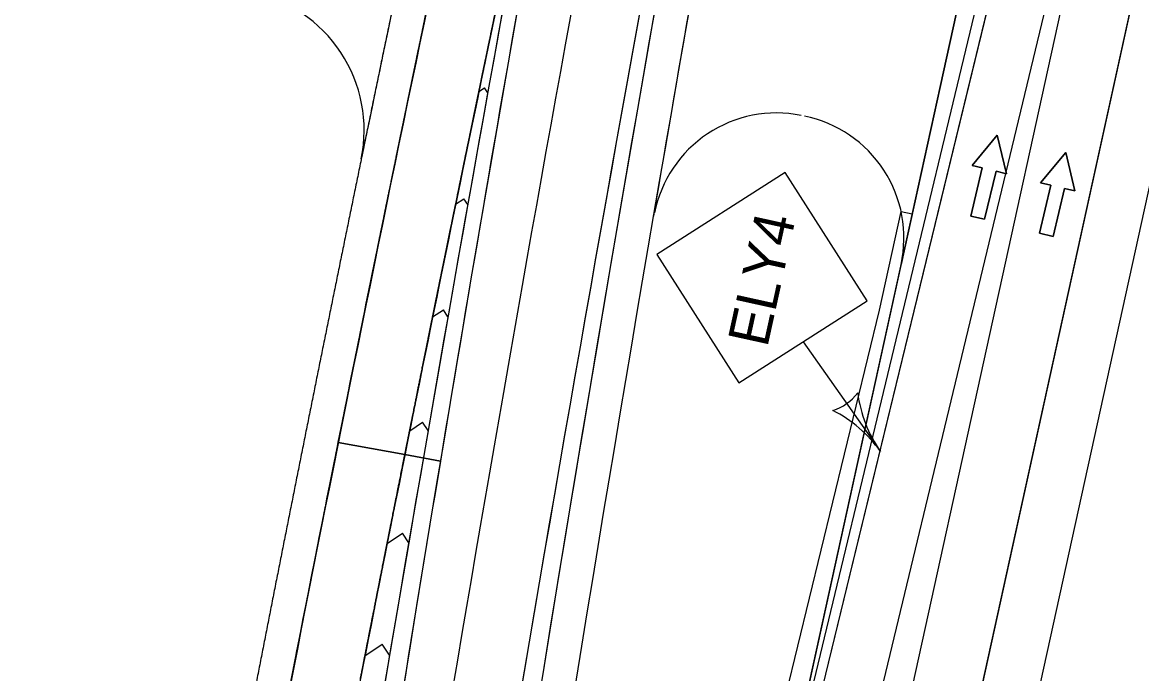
# Model space of a CAD drawing. Extents: x 14104283 to 14120882, y 8635219 to 8671666.
# Drawn here: x 14107950.2 to 14108148.5, y 8640439.5 to 8640554.9 of the extents above; entities that cross this region are included whole.
import ezdxf

# ---------------------------------------------------------------- set-up
doc = ezdxf.new("R2010")
doc.units = 0
for name, color, linetype in [('Cell', 7, 'Continuous'), ('dsnPaintExistingBrokenLaneLineWhite', 7, 'Continuous'), ('dsnPaintExistingChannelizingLaneWhite', 7, 'Continuous'), ('dsnPaintExistingEdgeLineRightWhite', 7, 'Continuous'), ('dsnPaintPlaceBrokenLaneLineWhite', 7, 'Continuous'), ('dsnPaintPlaceEdgeLineLeftYellow', 7, 'Continuous'), ('dsnPaintPlaceEdgeLineRightWhite', 7, 'Continuous'), ('dsnShadingPaved', 7, 'Continuous'), ('dsnStdLabel', 7, 'Continuous'), ('dsnStgShadingPrevPav', 7, 'Continuous'), ('dsnTapeRemoveChannelizingWhite', 7, 'Continuous'), ('dsnTapeRemoveChannelizingYellow', 7, 'Continuous')]:
    doc.layers.add(name, color=color, linetype=linetype)

msp = doc.modelspace()

# ---------------------------------------------------------------- linework, layer by layer
at = {"layer": 'Cell'}
for points in [[(14108120.71, 8640519.98), (14108118.28, 8640520.56), (14108120.3, 8640529.07), (14108118.48, 8640529.51), (14108122.96, 8640534.87), (14108124.56, 8640528.06), (14108122.73, 8640528.5)], [(14108132.84, 8640516.93), (14108130.41, 8640517.5), (14108132.43, 8640526.02), (14108130.61, 8640526.45), (14108135.09, 8640531.81), (14108136.69, 8640525.01), (14108134.86, 8640525.44)]]:
    msp.add_lwpolyline(points, close=True, dxfattribs=at)
for points in [[(14108122.73, 8640528.5), (14108124.56, 8640528.06), (14108122.96, 8640534.87), (14108118.48, 8640529.51), (14108120.3, 8640529.07), (14108118.28, 8640520.56), (14108120.71, 8640519.98), (14108122.73, 8640528.5)], [(14108134.86, 8640525.44), (14108136.69, 8640525.01), (14108135.09, 8640531.81), (14108130.61, 8640526.45), (14108132.43, 8640526.02), (14108130.41, 8640517.5), (14108132.84, 8640516.93), (14108134.86, 8640525.44)]]:
    msp.add_lwpolyline(points, dxfattribs=at)
at = {"layer": 'dsnPaintExistingBrokenLaneLineWhite'}
msp.add_arc((14117394.14, 8638857.08), 9500, 167.610212, 171.325989, dxfattribs=at)
at = {"layer": 'dsnPaintExistingChannelizingLaneWhite'}
for p, q in [((14108031.08, 8640542.65), (14108032.04, 8640543.28)), ((14108032.63, 8640542.38), (14108032.04, 8640543.28)), ((14108026.95, 8640522.65), (14108028.41, 8640523.61)), ((14108029.08, 8640522.59), (14108028.41, 8640523.61)), ((14108022.87, 8640502.69), (14108024.77, 8640503.94)), ((14108025.58, 8640502.72), (14108024.77, 8640503.94)), ((14108018.8, 8640482.51), (14108021.1, 8640484.04)), ((14108022.06, 8640482.58), (14108021.1, 8640484.04)), ((14108014.81, 8640462.56), (14108017.51, 8640464.36)), ((14108018.63, 8640462.68), (14108017.51, 8640464.36)), ((14108010.88, 8640442.64), (14108013.92, 8640444.69)), ((14108015.24, 8640442.73), (14108013.92, 8640444.69))]:
    msp.add_line(p, q, dxfattribs=at)
for centre, radius, start, end in [((14117394.14, 8638857.08), 9512, 169.444425, 171.325989), ((14117342.69, 8638609.63), 9510.13, 167.921867, 168.915877)]:
    msp.add_arc(centre, radius, start, end, dxfattribs=at)
at = {"layer": 'dsnPaintExistingEdgeLineRightWhite'}
for centre, radius, start, end in [((14117342.69, 8638609.63), 9522.13, 167.509575, 168.915877), ((14117350.61, 8638608.07), 9530.2, 168.915826, 170.320937)]:
    msp.add_arc(centre, radius, start, end, dxfattribs=at)
at = {"layer": 'dsnPaintPlaceBrokenLaneLineWhite'}
msp.add_line((14108099.08, 8640397.01), (14108184.86, 8640787.53), dxfattribs=at)
at = {"layer": 'dsnPaintPlaceEdgeLineLeftYellow'}
msp.add_line((14108046.49, 8640249.83), (14108129.2, 8640590.05), dxfattribs=at)
msp.add_arc((14117502.5, 8638839.63), 9597.75, 167.26751, 171.3206, dxfattribs=at)
at = {"layer": 'dsnPaintPlaceEdgeLineRightWhite'}
msp.add_line((14108110.8, 8640394.44), (14108196.58, 8640784.95), dxfattribs=at)
at = {"layer": 'dsnShadingPaved'}
msp.add_lwpolyline([(14108083.12, 8640400.52), (14108129.2, 8640590.05), (14108151.72, 8640692.57), (14108163.38, 8640689.76), (14108196.58, 8640784.95), (14108110.8, 8640394.44)], close=True, dxfattribs=at)
for centre, radius, start, end in [((14117502.5, 8638839.63), 9597.75, 167.266653, 171.3206), ((14117394.14, 8638857.08), 9512, 167.610212, 171.325989), ((14117394.14, 8638857.08), 9500, 167.610212, 171.325989), ((14117394.14, 8638857.08), 9500, 167.610212, 171.325989), ((14117342.69, 8638609.63), 9522.13, 167.509575, 168.915877), ((14117342.69, 8638609.63), 9510.13, 167.921867, 168.915877), ((14117350.61, 8638608.07), 9530.2, 168.915826, 170.320937)]:
    msp.add_arc(centre, radius, start, end, dxfattribs=at)
at = {"layer": 'dsnStdLabel'}
msp.add_line((14108088.52, 8640498.27), (14108102.24, 8640478.84), dxfattribs=at)
msp.add_lwpolyline([(14108077.14, 8640491), (14108099.89, 8640505.55), (14108085.34, 8640528.29), (14108062.59, 8640513.74)], close=True, dxfattribs=at)
for centre, radius, start, end in [((14108091.14, 8640494.55), 8.86, 287.4986, 322.9671), ((14108120.99, 8640492.08), 22.95, 187.1617, 215.233), ((14108083.5, 8640465.6), 22.95, 35.2328, 63.3041)]:
    msp.add_arc(centre, radius, start, end, dxfattribs=at)
at = {"layer": 'dsnStgShadingPrevPav'}
for p, q in [((14108124.35, 8640595.95), (14108105.9, 8640511.97)), ((14108006.14, 8640480.41), (14108017.94, 8640478.29)), ((14108017.94, 8640478.29), (14108006.14, 8640480.41)), ((14108017.94, 8640478.29), (14108024.25, 8640477.15)), ((14108024.25, 8640477.15), (14108017.94, 8640478.29))]:
    msp.add_line(p, q, dxfattribs=at)
for points in [[(14108081.5, 8640400.87), (14108123.34, 8640591.33), (14108126.55, 8640605.98), (14108216.67, 8641016.2), (14108268.16, 8641250.61), (14108382.95, 8641773.15), (14108422.02, 8641764.57), (14108309.38, 8641251.8), (14108270.22, 8641073.55), (14108265.93, 8641054.01), (14108255.74, 8641007.62), (14108202.1, 8640763.44), (14108120.56, 8640392.29)], [(14108077.26, 8640401.8), (14108102.07, 8640503.86), (14108105.91, 8640521.35), (14108107.87, 8640520.92), (14108081.5, 8640400.87)]]:
    msp.add_lwpolyline(points, close=True, dxfattribs=at)
for centre, radius, start, end in [((14117407.82, 8638919.35), 9488, 167.610212, 172.222077), ((14117407.82, 8638919.35), 9482, 167.610212, 172.222077), ((14117407.82, 8638919.35), 9512, 169.413861, 172.222077), ((14117407.82, 8638919.35), 9512, 169.413861, 170.574102), ((14117407.82, 8638919.35), 9488, 169.413861, 172.222077), ((14117407.82, 8638919.35), 9482, 169.768725, 170.278029), ((14107985.74, 8640535.75), 25, 348.3681, 78.5089), ((14108083.79, 8640516.82), 22, 78.4908, 168.7454), ((14108084.41, 8640516.69), 22, 347.6102, 78.4908), ((14117407.82, 8638919.35), 9512, 170.574102, 171.702544)]:
    msp.add_arc(centre, radius, start, end, dxfattribs=at)
for points, degree in [([(14108040.07, 8640670.33), (14108039.11, 8640666.01), (14108035.79, 8640651.03), (14108029.85, 8640623.7), (14108025.19, 8640602.04), (14108020.26, 8640578.84), (14108015.47, 8640556.04), (14108010.72, 8640533.12), (14108006.03, 8640510.22), (14108001.39, 8640487.29), (14107996.81, 8640464.36), (14107992.28, 8640441.41), (14107987.82, 8640418.46), (14107983.4, 8640395.49), (14107979.05, 8640372.51), (14107974.75, 8640349.53), (14107970.51, 8640326.51), (14107966.33, 8640303.59), (14107962.15, 8640280.24), (14107958.29, 8640258.43), (14107953.48, 8640230.88), (14107950.9, 8640215.75), (14107950.15, 8640211.39)], 2), ([(14107956.07, 8640210.37), (14107957.38, 8640218.06), (14107960.02, 8640233.43), (14107964.04, 8640256.47), (14107968.11, 8640279.5), (14107972.24, 8640302.51), (14107976.42, 8640325.52), (14107980.66, 8640348.51), (14107984.96, 8640371.49), (14107989.32, 8640394.46), (14107993.73, 8640417.41), (14107998.19, 8640440.35), (14108002.71, 8640463.28), (14108007.29, 8640486.2), (14108011.92, 8640509.1), (14108016.61, 8640531.99), (14108021.36, 8640554.87), (14108026.16, 8640577.73), (14108031.01, 8640600.58), (14108035.93, 8640623.41), (14108040.89, 8640646.24), (14108044.25, 8640661.44), (14108045.92, 8640669.04)], 3), ([(14108026.65, 8640608.79), (14108026.14, 8640606.46), (14108024.06, 8640596.74), (14108020.26, 8640578.84), (14108015.47, 8640556.04), (14108012.14, 8640539.95), (14108010.4, 8640531.51), (14108010.23, 8640530.71)], 3), ([(14108034.62, 8640559.66), (14108034.22, 8640557.75), (14108033.82, 8640555.85), (14108033.43, 8640553.95)], 2), ([(14108033.43, 8640553.95), (14108033.82, 8640555.85), (14108034.22, 8640557.75), (14108034.62, 8640559.66)], 2), ([(14108021.37, 8640554.87), (14108021.45, 8640555.25), (14108021.52, 8640555.63), (14108021.6, 8640556.01)], 2), ([(14108020.17, 8640549.15), (14108020.57, 8640551.05), (14108020.97, 8640552.96), (14108021.37, 8640554.87)], 2), ([(14108033.43, 8640553.95), (14108033.35, 8640553.57), (14108033.27, 8640553.19), (14108033.19, 8640552.81)], 2), ([(14108033.19, 8640552.81), (14108033.27, 8640553.19), (14108033.35, 8640553.57), (14108033.43, 8640553.95)], 2), ([(14108033.19, 8640552.81), (14108032.87, 8640551.28), (14108032.55, 8640549.76), (14108032.24, 8640548.24)], 2), ([(14108032.24, 8640548.24), (14108032.55, 8640549.76), (14108032.87, 8640551.28), (14108033.19, 8640552.81)], 2), ([(14108019.7, 8640546.86), (14108019.78, 8640547.24), (14108019.86, 8640547.62), (14108019.94, 8640548)], 2), ([(14108019.94, 8640548), (14108020.02, 8640548.39), (14108020.09, 8640548.77), (14108020.17, 8640549.15)], 2), ([(14108032.24, 8640548.24), (14108032.16, 8640547.86), (14108032.08, 8640547.48), (14108032, 8640547.1)], 2), ([(14108032, 8640547.1), (14108032.08, 8640547.48), (14108032.16, 8640547.86), (14108032.24, 8640548.24)], 2), ([(14108018.99, 8640543.43), (14108019.22, 8640544.57), (14108019.46, 8640545.72), (14108019.7, 8640546.86)], 2), ([(14108032, 8640547.1), (14108031.84, 8640546.33), (14108031.68, 8640545.57), (14108031.52, 8640544.81)], 2), ([(14108031.52, 8640544.81), (14108031.68, 8640545.57), (14108031.84, 8640546.33), (14108032, 8640547.1)], 2), ([(14108018.75, 8640542.29), (14108018.83, 8640542.67), (14108018.91, 8640543.05), (14108018.99, 8640543.43)], 2), ([(14108031.52, 8640544.81), (14108031.21, 8640543.29), (14108030.89, 8640541.77), (14108030.57, 8640540.24)], 2), ([(14108030.57, 8640540.24), (14108030.89, 8640541.77), (14108031.21, 8640543.29), (14108031.52, 8640544.81)], 2), ([(14108018.28, 8640540), (14108018.43, 8640540.76), (14108018.59, 8640541.52), (14108018.75, 8640542.29)], 2), ([(14108017.33, 8640535.42), (14108017.64, 8640536.95), (14108017.96, 8640538.47), (14108018.28, 8640540)], 2), ([(14108030.57, 8640540.24), (14108030.42, 8640539.48), (14108030.26, 8640538.72), (14108030.1, 8640537.96)], 2), ([(14108030.1, 8640537.96), (14108030.26, 8640538.72), (14108030.42, 8640539.48), (14108030.57, 8640540.24)], 2), ([(14108030.1, 8640537.96), (14108029.71, 8640536.05), (14108029.31, 8640534.15), (14108028.92, 8640532.24)], 2), ([(14108028.92, 8640532.24), (14108029.31, 8640534.15), (14108029.71, 8640536.05), (14108030.1, 8640537.96)], 2), ([(14108016.86, 8640533.13), (14108017.01, 8640533.9), (14108017.17, 8640534.66), (14108017.33, 8640535.42)], 2), ([(14108016.39, 8640530.85), (14108016.46, 8640531.23), (14108016.54, 8640531.61), (14108016.62, 8640531.99)], 2), ([(14108016.62, 8640531.99), (14108016.7, 8640532.37), (14108016.78, 8640532.75), (14108016.86, 8640533.13)], 2), ([(14108028.92, 8640532.24), (14108028.76, 8640531.48), (14108028.6, 8640530.72), (14108028.45, 8640529.96)], 2), ([(14108028.45, 8640529.96), (14108028.6, 8640530.72), (14108028.76, 8640531.48), (14108028.92, 8640532.24)], 2), ([(14108014.97, 8640523.98), (14108015.44, 8640526.27), (14108015.91, 8640528.56), (14108016.39, 8640530.85)], 2), ([(14108028.45, 8640529.96), (14108028.37, 8640529.58), (14108028.29, 8640529.2), (14108028.21, 8640528.82)], 2), ([(14108028.21, 8640528.82), (14108028.29, 8640529.2), (14108028.37, 8640529.58), (14108028.45, 8640529.96)], 2), ([(14108028.21, 8640528.82), (14108027.82, 8640526.91), (14108027.43, 8640525.01), (14108027.04, 8640523.1)], 2), ([(14108027.04, 8640523.1), (14108027.43, 8640525.01), (14108027.82, 8640526.91), (14108028.21, 8640528.82)], 2), ([(14108014.74, 8640522.84), (14108014.82, 8640523.22), (14108014.9, 8640523.6), (14108014.97, 8640523.98)], 2), ([(14108013.33, 8640515.97), (14108013.8, 8640518.26), (14108014.27, 8640520.55), (14108014.74, 8640522.84)], 2), ([(14108027.04, 8640523.1), (14108026.72, 8640521.58), (14108026.41, 8640520.05), (14108026.1, 8640518.53)], 2), ([(14108026.1, 8640518.53), (14108026.41, 8640520.05), (14108026.72, 8640521.58), (14108027.04, 8640523.1)], 2), ([(14108026.1, 8640518.53), (14108026.02, 8640518.15), (14108025.94, 8640517.77), (14108025.86, 8640517.39)], 2), ([(14108025.86, 8640517.39), (14108025.94, 8640517.77), (14108026.02, 8640518.15), (14108026.1, 8640518.53)], 2), ([(14108012.4, 8640511.39), (14108012.71, 8640512.92), (14108013.02, 8640514.44), (14108013.33, 8640515.97)], 2), ([(14108025.86, 8640517.39), (14108025.71, 8640516.63), (14108025.55, 8640515.86), (14108025.4, 8640515.1)], 2), ([(14108025.4, 8640515.1), (14108025.55, 8640515.86), (14108025.71, 8640516.63), (14108025.86, 8640517.39)], 2), ([(14108025.4, 8640515.1), (14108025.24, 8640514.34), (14108025.09, 8640513.58), (14108024.93, 8640512.81)], 2), ([(14108024.93, 8640512.81), (14108025.09, 8640513.58), (14108025.24, 8640514.34), (14108025.4, 8640515.1)], 2), ([(14108024.93, 8640512.81), (14108024.7, 8640511.67), (14108024.46, 8640510.53), (14108024.23, 8640509.38)], 2), ([(14108024.23, 8640509.38), (14108024.46, 8640510.53), (14108024.7, 8640511.67), (14108024.93, 8640512.81)], 2), ([(14108011.93, 8640509.1), (14108012.01, 8640509.48), (14108012.09, 8640509.86), (14108012.17, 8640510.25)], 2), ([(14108012.17, 8640510.25), (14108012.24, 8640510.63), (14108012.32, 8640511.01), (14108012.4, 8640511.39)], 2), ([(14108011.47, 8640506.81), (14108011.62, 8640507.57), (14108011.78, 8640508.34), (14108011.93, 8640509.1)], 2), ([(14108024, 8640508.24), (14108023.92, 8640507.86), (14108023.84, 8640507.48), (14108023.76, 8640507.1)], 2), ([(14108023.76, 8640507.1), (14108023.84, 8640507.48), (14108023.92, 8640507.86), (14108024, 8640508.24)], 2), ([(14108024.23, 8640509.38), (14108024.15, 8640509), (14108024.07, 8640508.62), (14108024, 8640508.24)], 2), ([(14108024, 8640508.24), (14108024.07, 8640508.62), (14108024.15, 8640509), (14108024.23, 8640509.38)], 2), ([(14108010.77, 8640503.38), (14108011, 8640504.52), (14108011.23, 8640505.67), (14108011.47, 8640506.81)], 2), ([(14108023.53, 8640505.95), (14108023.45, 8640505.57), (14108023.38, 8640505.19), (14108023.3, 8640504.81)], 2), ([(14108023.3, 8640504.81), (14108023.38, 8640505.19), (14108023.45, 8640505.57), (14108023.53, 8640505.95)], 2), ([(14108023.76, 8640507.1), (14108023.69, 8640506.72), (14108023.61, 8640506.34), (14108023.53, 8640505.95)], 2), ([(14108023.53, 8640505.95), (14108023.61, 8640506.34), (14108023.69, 8640506.72), (14108023.76, 8640507.1)], 2), ([(14108023.07, 8640503.67), (14108022.99, 8640503.29), (14108022.91, 8640502.91), (14108022.83, 8640502.52)], 2), ([(14108022.83, 8640502.52), (14108022.91, 8640502.91), (14108022.99, 8640503.29), (14108023.07, 8640503.67)], 2), ([(14108023.3, 8640504.81), (14108023.22, 8640504.43), (14108023.14, 8640504.05), (14108023.07, 8640503.67)], 2), ([(14108023.07, 8640503.67), (14108023.14, 8640504.05), (14108023.22, 8640504.43), (14108023.3, 8640504.81)], 2), ([(14108010.3, 8640501.09), (14108010.46, 8640501.85), (14108010.61, 8640502.61), (14108010.77, 8640503.38)], 2), ([(14108022.83, 8640502.52), (14108022.76, 8640502.14), (14108022.68, 8640501.76), (14108022.6, 8640501.38)], 2), ([(14108022.6, 8640501.38), (14108022.68, 8640501.76), (14108022.76, 8640502.14), (14108022.83, 8640502.52)], 2), ([(14108009.38, 8640496.5), (14108009.69, 8640498.03), (14108009.99, 8640499.56), (14108010.3, 8640501.09)], 2), ([(14108022.37, 8640500.24), (14108021.98, 8640498.33), (14108021.6, 8640496.43), (14108021.21, 8640494.52)], 2), ([(14108021.21, 8640494.52), (14108021.6, 8640496.43), (14108021.98, 8640498.33), (14108022.37, 8640500.24)], 2), ([(14108022.6, 8640501.38), (14108022.52, 8640501), (14108022.45, 8640500.62), (14108022.37, 8640500.24)], 2), ([(14108022.37, 8640500.24), (14108022.45, 8640500.62), (14108022.52, 8640501), (14108022.6, 8640501.38)], 2), ([(14108009.15, 8640495.36), (14108009.22, 8640495.74), (14108009.3, 8640496.12), (14108009.38, 8640496.5)], 2), ([(14108008.45, 8640491.92), (14108008.68, 8640493.07), (14108008.91, 8640494.21), (14108009.15, 8640495.36)], 2), ([(14108021.21, 8640494.52), (14108020.52, 8640491.09), (14108019.83, 8640487.66), (14108019.14, 8640484.22)], 2), ([(14108019.14, 8640484.22), (14108019.83, 8640487.66), (14108020.52, 8640491.09), (14108021.21, 8640494.52)], 2), ([(14108007.99, 8640489.63), (14108008.14, 8640490.4), (14108008.3, 8640491.16), (14108008.45, 8640491.92)], 2), ([(14108007.53, 8640487.34), (14108007.61, 8640487.72), (14108007.68, 8640488.11), (14108007.76, 8640488.49)], 2), ([(14108007.76, 8640488.49), (14108007.84, 8640488.87), (14108007.91, 8640489.25), (14108007.99, 8640489.63)], 2), ([(14108006.84, 8640483.91), (14108006.99, 8640484.67), (14108007.15, 8640485.43), (14108007.3, 8640486.2)], 2), ([(14108007.3, 8640486.2), (14108007.38, 8640486.58), (14108007.45, 8640486.96), (14108007.53, 8640487.34)], 2), ([(14108006.38, 8640481.61), (14108006.53, 8640482.38), (14108006.69, 8640483.14), (14108006.84, 8640483.91)], 2), ([(14108019.14, 8640484.22), (14108019.06, 8640483.84), (14108018.98, 8640483.46), (14108018.91, 8640483.08)], 2), ([(14108018.91, 8640483.08), (14108018.98, 8640483.46), (14108019.06, 8640483.84), (14108019.14, 8640484.22)], 2), ([(14108018.91, 8640483.08), (14108018.75, 8640482.32), (14108018.6, 8640481.55), (14108018.45, 8640480.79)], 2), ([(14108018.45, 8640480.79), (14108018.6, 8640481.55), (14108018.75, 8640482.32), (14108018.91, 8640483.08)], 2), ([(14108005.46, 8640477.03), (14108005.69, 8640478.16), (14108005.91, 8640479.28), (14108006.14, 8640480.41)], 2), ([(14108006.14, 8640480.41), (14108006.22, 8640480.81), (14108006.3, 8640481.21), (14108006.38, 8640481.61)], 2), ([(14108018.45, 8640480.79), (14108018.29, 8640480.03), (14108018.14, 8640479.27), (14108017.99, 8640478.5)], 2), ([(14108017.99, 8640478.5), (14108018.14, 8640479.27), (14108018.29, 8640480.03), (14108018.45, 8640480.79)], 2), ([(14108017.94, 8640478.29), (14108017.88, 8640477.98), (14108017.82, 8640477.67), (14108017.76, 8640477.36)], 2), ([(14108017.76, 8640477.36), (14108017.82, 8640477.67), (14108017.88, 8640477.98), (14108017.94, 8640478.29)], 2), ([(14108017.99, 8640478.5), (14108017.97, 8640478.43), (14108017.96, 8640478.36), (14108017.94, 8640478.29)], 2), ([(14108017.94, 8640478.29), (14108017.96, 8640478.36), (14108017.97, 8640478.43), (14108017.99, 8640478.5)], 2), ([(14108005, 8640474.74), (14108005.08, 8640475.12), (14108005.16, 8640475.5), (14108005.23, 8640475.89)], 2), ([(14108005.23, 8640475.89), (14108005.31, 8640476.27), (14108005.38, 8640476.65), (14108005.46, 8640477.03)], 2), ([(14108017.53, 8640476.22), (14108016.84, 8640472.78), (14108016.16, 8640469.35), (14108015.47, 8640465.92)], 2), ([(14108015.47, 8640465.92), (14108016.16, 8640469.35), (14108016.84, 8640472.78), (14108017.53, 8640476.22)], 2), ([(14108017.76, 8640477.36), (14108017.68, 8640476.98), (14108017.61, 8640476.6), (14108017.53, 8640476.22)], 2), ([(14108017.53, 8640476.22), (14108017.61, 8640476.6), (14108017.68, 8640476.98), (14108017.76, 8640477.36)], 2), ([(14108003.63, 8640467.87), (14108004.09, 8640470.16), (14108004.55, 8640472.45), (14108005, 8640474.74)], 2), ([(14108002.72, 8640463.28), (14108002.95, 8640464.43), (14108003.18, 8640465.57), (14108003.4, 8640466.72)], 2), ([(14108003.4, 8640466.72), (14108003.48, 8640467.1), (14108003.56, 8640467.48), (14108003.63, 8640467.87)], 2), ([(14108015.47, 8640465.92), (14108015.4, 8640465.53), (14108015.32, 8640465.15), (14108015.25, 8640464.77)], 2), ([(14108015.25, 8640464.77), (14108015.32, 8640465.15), (14108015.4, 8640465.53), (14108015.47, 8640465.92)], 2), ([(14108015.25, 8640464.77), (14108015.17, 8640464.39), (14108015.09, 8640464.01), (14108015.02, 8640463.63)], 2), ([(14108015.02, 8640463.63), (14108015.09, 8640464.01), (14108015.17, 8640464.39), (14108015.25, 8640464.77)], 2), ([(14108002.27, 8640460.99), (14108002.34, 8640461.37), (14108002.42, 8640461.75), (14108002.49, 8640462.13)], 2), ([(14108002.49, 8640462.13), (14108002.57, 8640462.52), (14108002.65, 8640462.9), (14108002.72, 8640463.28)], 2), ([(14108015.02, 8640463.63), (14108014.87, 8640462.86), (14108014.71, 8640462.1), (14108014.56, 8640461.34)], 2), ([(14108014.56, 8640461.34), (14108014.71, 8640462.1), (14108014.87, 8640462.86), (14108015.02, 8640463.63)], 2), ([(14108002.04, 8640459.84), (14108002.12, 8640460.22), (14108002.19, 8640460.61), (14108002.27, 8640460.99)], 2), ([(14108014.56, 8640461.34), (14108014.41, 8640460.57), (14108014.26, 8640459.81), (14108014.11, 8640459.05)], 2), ([(14108014.11, 8640459.05), (14108014.26, 8640459.81), (14108014.41, 8640460.57), (14108014.56, 8640461.34)], 2), ([(14108001.13, 8640455.26), (14108001.43, 8640456.79), (14108001.74, 8640458.31), (14108002.04, 8640459.84)], 2), ([(14108014.11, 8640459.05), (14108013.5, 8640455.99), (14108012.9, 8640452.94), (14108012.3, 8640449.89)], 2), ([(14108012.3, 8640449.89), (14108012.9, 8640452.94), (14108013.5, 8640455.99), (14108014.11, 8640459.05)], 2), ([(14107999.78, 8640448.38), (14108000.15, 8640450.29), (14108000.53, 8640452.2), (14108000.91, 8640454.11)], 2), ([(14108000.91, 8640454.11), (14108000.98, 8640454.49), (14108001.06, 8640454.87), (14108001.13, 8640455.26)], 2), ([(14107999.55, 8640447.23), (14107999.63, 8640447.61), (14107999.7, 8640448), (14107999.78, 8640448.38)], 2), ([(14108012.3, 8640449.89), (14108011.92, 8640447.98), (14108011.55, 8640446.07), (14108011.17, 8640444.16)], 2), ([(14108011.17, 8640444.16), (14108011.55, 8640446.07), (14108011.92, 8640447.98), (14108012.3, 8640449.89)], 2), ([(14107998.87, 8640443.79), (14107999.1, 8640444.94), (14107999.33, 8640446.09), (14107999.55, 8640447.23)], 2), ([(14108011.17, 8640444.16), (14108010.87, 8640442.64), (14108010.57, 8640441.11), (14108010.27, 8640439.58)], 2), ([(14108010.27, 8640439.58), (14108010.57, 8640441.11), (14108010.87, 8640442.64), (14108011.17, 8640444.16)], 2), ([(14107998.2, 8640440.35), (14107998.42, 8640441.5), (14107998.65, 8640442.65), (14107998.87, 8640443.79)], 2), ([(14107997.98, 8640439.2), (14107998.05, 8640439.59), (14107998.13, 8640439.97), (14107998.2, 8640440.35)], 2), ([(14108010.27, 8640439.58), (14108010.2, 8640439.2), (14108010.12, 8640438.82), (14108010.05, 8640438.44)], 2), ([(14108010.05, 8640438.44), (14108010.12, 8640438.82), (14108010.2, 8640439.2), (14108010.27, 8640439.58)], 2)]:
    msp.add_open_spline(points, degree=degree, dxfattribs=at)
at = {"layer": 'dsnTapeRemoveChannelizingWhite'}
msp.add_line((14108093.19, 8640398.18), (14108163.38, 8640689.76), dxfattribs=at)
at = {"layer": 'dsnTapeRemoveChannelizingYellow'}
msp.add_line((14108081.5, 8640400.87), (14108151.72, 8640692.57), dxfattribs=at)

# ---------------------------------------------------------------- texts
at = {"layer": 'dsnStdLabel'}
msp.add_text('ELY4', height=7.2, rotation=77.6078, dxfattribs=at).set_placement((14108082.17, 8640497.09))

doc.saveas('drawing.dxf')
